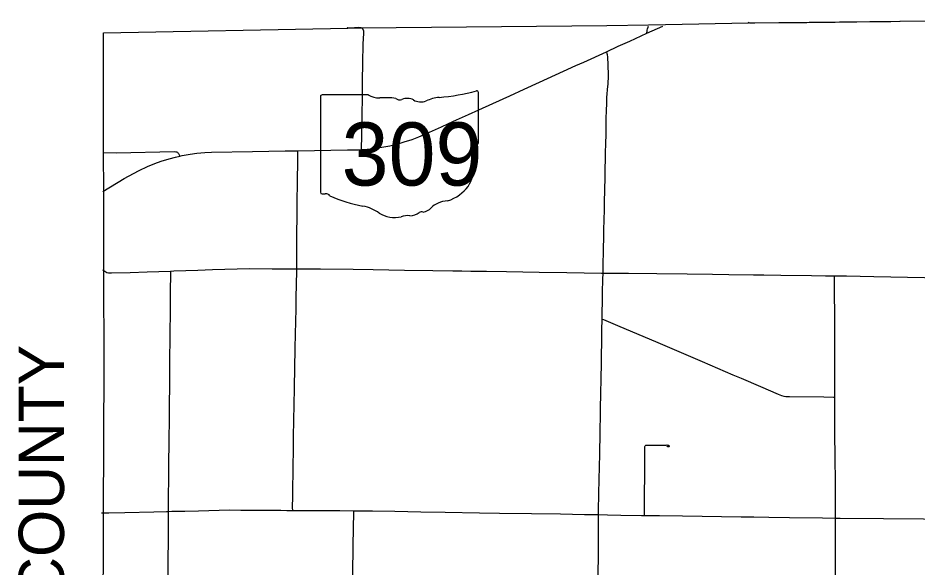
# Model space of a CAD drawing. Extents: x 9078 to 9739, y 4248 to 4966.
# Drawn here: x 9197.5 to 9296.8, y 4760.2 to 4820.8 of the extents above; entities that cross this region are included whole.
import ezdxf

# ---------------------------------------------------------------- set-up
doc = ezdxf.new("R2010")
doc.units = 0
for name, color, linetype in [('GM_X_Adjacent_County_Text', 7, 'Continuous'), ('GM_X_County', 7, 'Continuous'), ('GM_X_County_Road', 7, 'Continuous'), ('GM_X_State_Route', 7, 'Continuous'), ('GM_X_State_Shield', 7, 'Continuous'), ('GM_X_Township', 7, 'Continuous'), ('GM_X_Township_Road', 7, 'Continuous')]:
    doc.layers.add(name, color=color, linetype=linetype)

msp = doc.modelspace()

# ---------------------------------------------------------------- linework, layer by layer
at = {"layer": 'GM_X_County'}
msp.add_lwpolyline([(9206.245, 4660.249), (9206.809, 4712.196), (9206.887, 4739.703), (9206.961, 4766.011), (9207.008, 4782.44), (9206.987, 4792.874), (9206.968, 4801.71), (9206.96, 4805.912), (9206.933, 4819.119), (9233.899, 4819.643), (9235.353, 4819.689), (9262.437, 4819.962), (9267.039, 4820.02), (9268.93, 4820.044), (9278.09, 4820.249), (9301.491, 4820.507)], dxfattribs=at)
at = {"layer": 'GM_X_County_Road'}
for points in [[(9266.867, 4819.085), (9266.875, 4819.184), (9266.884, 4819.265), (9266.892, 4819.336), (9266.906, 4819.423), (9266.948, 4819.575), (9267.002, 4819.746), (9267.046, 4819.869)], [(9262.03, 4792.621), (9262.033, 4792.748), (9262.033, 4793.241), (9262.087, 4795.371), (9262.109, 4796.519), (9262.124, 4797.339), (9262.154, 4798.569), (9262.179, 4799.553), (9262.199, 4800.455), (9262.259, 4803.161), (9262.277, 4804.227), (9262.291, 4805.13), (9262.313, 4806.032), (9262.331, 4806.77), (9262.363, 4808.081), (9262.376, 4808.819), (9262.393, 4809.807), (9262.417, 4810.457), (9262.44, 4811.441), (9262.455, 4812.014), (9262.475, 4812.424), (9262.51, 4812.833), (9262.561, 4813.239), (9262.59, 4813.444), (9262.617, 4813.749), (9262.644, 4814.13), (9262.653, 4814.399), (9262.635, 4814.754), (9262.607, 4815.305), (9262.585, 4815.866), (9262.576, 4816.211), (9262.558, 4816.503), (9262.54, 4816.7), (9262.507, 4816.819), (9262.475, 4816.894), (9262.408, 4817.054)], [(9206.838, 4793.004), (9207.079, 4792.834), (9207.202, 4792.757), (9207.329, 4792.701), (9207.502, 4792.666), (9207.825, 4792.65), (9209.876, 4792.714), (9211.761, 4792.773), (9214.354, 4792.86)], [(9214.354, 4792.86), (9214.714, 4792.872), (9217.337, 4792.962), (9218.977, 4793.027), (9221.684, 4793.108), (9223.079, 4793.126), (9225.541, 4793.112), (9227.018, 4793.11), (9228.25, 4793.107)], [(9228.25, 4793.107), (9230.874, 4793.1), (9234.484, 4793.066), (9236.7, 4793.032), (9240.14, 4792.973), (9243.258, 4792.92), (9245.472, 4792.887), (9246.457, 4792.878), (9247.441, 4792.863), (9249.164, 4792.833), (9251.379, 4792.806), (9253.184, 4792.779), (9254.988, 4792.745), (9258.024, 4792.703), (9261.879, 4792.619), (9262.03, 4792.621)], [(9261.94, 4787.57), (9261.952, 4788.236), (9261.982, 4789.548), (9261.988, 4790.537), (9262.019, 4791.94), (9262.03, 4792.621)], [(9262.03, 4792.621), (9263.028, 4792.633), (9264.833, 4792.609), (9267.951, 4792.582), (9271.314, 4792.54), (9274.104, 4792.509), (9275.909, 4792.488), (9278.616, 4792.45), (9279.764, 4792.435), (9281.652, 4792.424), (9285.016, 4792.381), (9286.574, 4792.35), (9287.552, 4792.339)], [(9287.6, 4778.956), (9287.592, 4780.367), (9287.586, 4784.141), (9287.586, 4787.26), (9287.555, 4791.199), (9287.551, 4792.182), (9287.552, 4792.339)], [(9287.552, 4792.339), (9288.871, 4792.322), (9291.906, 4792.252), (9297.485, 4792.142), (9301.094, 4792.076), (9301.315, 4792.078)], [(9261.534, 4765.997), (9261.548, 4766.423), (9261.583, 4768.309), (9261.608, 4769.868), (9261.666, 4772.656), (9261.703, 4775.035), (9261.752, 4777.167), (9261.768, 4778.233), (9261.775, 4778.807), (9261.792, 4779.708), (9261.813, 4780.61), (9261.83, 4781.348), (9261.848, 4782.331), (9261.87, 4783.561), (9261.891, 4785.038), (9261.917, 4786.35), (9261.94, 4787.57)], [(9261.94, 4787.57), (9262.083, 4787.51), (9263.903, 4786.754), (9267.832, 4785.079), (9272.963, 4782.878), (9276.361, 4781.431), (9277.267, 4781.043), (9279.381, 4780.139), (9281.338, 4779.286), (9281.722, 4779.141), (9281.96, 4779.077), (9282.203, 4779.037), (9282.613, 4779.011), (9286.391, 4778.975), (9287.458, 4778.958), (9287.6, 4778.956)], [(9287.676, 4765.616), (9287.674, 4765.813), (9287.666, 4767.372), (9287.664, 4767.864), (9287.65, 4769.176), (9287.651, 4770.161), (9287.63, 4771.706), (9287.623, 4772.607), (9287.613, 4773.104), (9287.617, 4773.151), (9287.615, 4773.31), (9287.612, 4773.963), (9287.605, 4774.706), (9287.6, 4774.87), (9287.598, 4775.362), (9287.597, 4776.182), (9287.598, 4777.413), (9287.603, 4778.561), (9287.6, 4778.956)], [(9214.117, 4766.345), (9214.473, 4766.365), (9215.934, 4766.389), (9217.41, 4766.416), (9218.558, 4766.446), (9220.854, 4766.507), (9222.084, 4766.497), (9223.642, 4766.493), (9225.282, 4766.47), (9226.513, 4766.47), (9227.168, 4766.464), (9227.814, 4766.457)], [(9227.814, 4766.457), (9228.399, 4766.451), (9229.957, 4766.451), (9231.68, 4766.445), (9232.992, 4766.444), (9234.551, 4766.426)], [(9234.551, 4766.426), (9235.206, 4766.419), (9236.601, 4766.4), (9239.061, 4766.361), (9241.932, 4766.309), (9244.639, 4766.267), (9248.411, 4766.208), (9250.626, 4766.167), (9254.153, 4766.105), (9257.352, 4766.066), (9259.976, 4766.011), (9261.534, 4765.997)], [(9261.375, 4739.312), (9261.377, 4739.518), (9261.383, 4740.831), (9261.394, 4742.225), (9261.402, 4742.963), (9261.412, 4744.194), (9261.418, 4745.588), (9261.425, 4746.819), (9261.437, 4748.213), (9261.443, 4749.28), (9261.447, 4750.592), (9261.459, 4752.396), (9261.467, 4753.053), (9261.472, 4754.939), (9261.477, 4756.498), (9261.482, 4757.318), (9261.496, 4758.384), (9261.508, 4759.779), (9261.518, 4761.173), (9261.517, 4762.568), (9261.542, 4765.275), (9261.534, 4765.997)], [(9261.534, 4765.997), (9262.518, 4765.973), (9263.994, 4765.948), (9266.291, 4765.916), (9266.607, 4765.912)], [(9266.607, 4765.912), (9268.26, 4765.889), (9270.802, 4765.853), (9277.281, 4765.754), (9278.676, 4765.742), (9280.316, 4765.716), (9282.613, 4765.682), (9286.222, 4765.632), (9287.676, 4765.616)], [(9287.625, 4738.92), (9287.624, 4739.144), (9287.623, 4739.882), (9287.641, 4744.068), (9287.647, 4746.612), (9287.653, 4750.633), (9287.653, 4752.356), (9287.649, 4753.587), (9287.646, 4754.407), (9287.665, 4756.294), (9287.676, 4758.428), (9287.668, 4759.494), (9287.676, 4760.479), (9287.676, 4763.105), (9287.684, 4764.992), (9287.676, 4765.616)], [(9287.676, 4765.616), (9288.19, 4765.61), (9292.948, 4765.561), (9297.377, 4765.528), (9300.166, 4765.491), (9301.395, 4765.471), (9303.609, 4765.433), (9305.413, 4765.391), (9307.803, 4765.355)]]:
    msp.add_lwpolyline(points, dxfattribs=at)
at = {"layer": 'GM_X_State_Route'}
for points in [[(9259.047, 4815.521), (9259.899, 4815.909), (9262.408, 4817.054), (9263.706, 4817.648), (9264.977, 4818.222), (9266.246, 4818.804), (9266.867, 4819.085), (9268.642, 4819.889)], [(9243.551, 4808.483), (9244.211, 4808.781), (9245.557, 4809.388), (9247.201, 4810.133), (9248.319, 4810.649), (9249.89, 4811.357), (9251.759, 4812.203), (9253.326, 4812.919), (9255.044, 4813.701), (9257.658, 4814.89), (9259.047, 4815.521)], [(9206.877, 4801.627), (9209.244, 4803.051), (9210.239, 4803.623), (9210.894, 4803.961), (9211.786, 4804.378), (9212.62, 4804.72), (9213.314, 4804.968), (9214.175, 4805.236), (9214.887, 4805.429), (9215.375, 4805.537), (9215.607, 4805.588), (9216.493, 4805.752), (9217.224, 4805.853), (9218.121, 4805.94), (9218.858, 4805.977), (9223.37, 4806.058), (9226.98, 4806.114), (9228.379, 4806.136), (9233.872, 4806.222), (9235.022, 4806.249), (9235.41, 4806.269), (9236.006, 4806.301), (9236.741, 4806.378), (9237.635, 4806.51), (9238.523, 4806.681), (9239.322, 4806.872), (9240.111, 4807.1), (9240.969, 4807.385), (9241.737, 4807.678), (9242.565, 4808.038), (9243.551, 4808.483)]]:
    msp.add_lwpolyline(points, dxfattribs=at)
at = {"layer": 'GM_X_State_Shield'}
for p, q in [((9248.286, 4807.03), (9248.286, 4812.557)), ((9230.884, 4812.114), (9230.884, 4801.547)), ((9236.152, 4812.295), (9231.055, 4812.295)), ((9248.284, 4807.031), (9248.286, 4807.03))]:
    msp.add_line(p, q, dxfattribs=at)
for centre, major_axis, start_param, end_param in [((9242.087, 4826.701), (18.455, 0), 4.814394, 5.042369), ((9248.093, 4812.58), (0.194, 0), 6.141152, 7.989035), ((9231.083, 4812.136), (0.202, 0), 1.712693, 3.28349), ((9237.365, 4813.522), (1.955, 0), 4.042523, 4.731795), ((9238.014, 4806.363), (7.02, 0), 1.404758, 1.657858), ((9239.607, 4812.191), (0.564, 0), 3.836095, 5.185415), ((9240.435, 4810.97), (1.173, 0), 0.950623, 2.079405), ((9241.949, 4812.645), (1.411, 0), 4.081561, 5.145723), ((9244.441, 4809.068), (3.713, 0), 1.699011, 2.107814), ((9248.241, 4806.624), (0.3, 0), 1.883978, 3.671073), ((9246.334, 4805.925), (1.8, 0), 5.934695, 6.695948), ((9248.079, 4807.008), (0.207, 0), 5.05454, 6.418171), ((9243.121, 4804.014), (4.616, 0), 5.101752, 6.440018), ((9248.98, 4804.717), (1.309, 0), 2.387724, 3.262537), ((9231.085, 4801.524), (0.203, 0), 3.00124, 4.508301), ((9231.116, 4802.605), (1.552, 0), 4.665946, 4.897461), ((9231.434, 4800.938), (0.56, 0), 0.519207, 1.627899), ((9238.5, 4810.431), (13.327, 0), 4.195997, 4.488961), ((9245.067, 4798.581), (2.528, 0), 1.647645, 2.488434), ((9234.526, 4796.8), (4.17, 0), 0.823519, 1.323587), ((9241.864, 4800.523), (1.491, 0), 4.937069, 5.64225), ((9239.036, 4800.885), (2.646, 0), 4.026481, 4.996735), ((9240.565, 4797.232), (2.174, 0), 1.495662, 1.94098), ((9240.758, 4800.094), (1.41, 0), 4.691044, 5.507374), ((9242.033, 4799.071), (0.397, 0), 1.147584, 2.315152)]:
    msp.add_ellipse(centre, major_axis=major_axis, ratio=0.8, start_param=start_param, end_param=end_param, dxfattribs=at)
at = {"layer": 'GM_X_Township'}
msp.add_lwpolyline([(9206.933, 4819.119), (9233.899, 4819.643), (9235.353, 4819.689), (9262.437, 4819.962), (9267.039, 4820.02), (9268.93, 4820.044), (9278.09, 4820.249), (9301.491, 4820.507), (9314.472, 4820.654), (9327.731, 4820.757), (9343.217, 4820.773), (9342.932, 4808.852), (9342.474, 4789.454), (9342.4, 4782.335), (9342.294, 4776.852), (9341.676, 4755.756), (9341.613, 4751.456), (9313.969, 4750.869), (9313.79, 4738.291), (9313.407, 4711.5), (9313.217, 4698.184)], dxfattribs=at)
at = {"layer": 'GM_X_Township_Road'}
for points in [[(9278.005, 4820.304), (9278.058, 4820.275), (9278.12, 4820.259), (9278.201, 4820.249), (9278.774, 4820.234), (9281.644, 4820.273), (9283.038, 4820.281), (9284.513, 4820.29), (9287.629, 4820.323), (9290.006, 4820.351), (9292.956, 4820.389), (9293.446, 4820.4), (9293.774, 4820.402), (9294.757, 4820.413), (9298.856, 4820.469), (9301.482, 4820.515)], [(9234.922, 4819.695), (9234.617, 4819.676), (9234.206, 4819.649), (9234.043, 4819.657), (9233.961, 4819.663), (9233.896, 4819.676), (9233.861, 4819.69), (9233.825, 4819.711)], [(9235.599, 4819.483), (9235.585, 4819.514), (9235.563, 4819.551), (9235.536, 4819.585), (9235.5, 4819.619), (9235.435, 4819.659), (9235.353, 4819.688), (9235.271, 4819.699), (9235.11, 4819.707), (9234.922, 4819.695)], [(9235.41, 4806.269), (9235.413, 4806.488), (9235.428, 4807.636), (9235.434, 4808.538), (9235.458, 4810.014), (9235.491, 4812.065), (9235.522, 4813.787), (9235.556, 4815.837), (9235.596, 4817.888), (9235.654, 4819.116), (9235.646, 4819.302), (9235.639, 4819.348), (9235.628, 4819.405), (9235.615, 4819.445), (9235.599, 4819.483)], [(9206.894, 4805.922), (9208.333, 4805.917), (9214.763, 4806.037), (9214.929, 4806.024), (9215.013, 4806.003), (9215.092, 4805.965), (9215.161, 4805.91), (9215.215, 4805.842), (9215.255, 4805.765), (9215.375, 4805.537)], [(9228.25, 4793.107), (9228.255, 4793.695), (9228.255, 4794.105), (9228.257, 4794.536), (9228.253, 4795.575), (9228.261, 4796.229), (9228.278, 4797.058), (9228.282, 4797.695), (9228.29, 4798.172), (9228.298, 4798.591), (9228.311, 4799.258), (9228.312, 4799.757), (9228.316, 4800.741), (9228.322, 4801.314), (9228.329, 4801.806), (9228.334, 4802.297), (9228.347, 4803.363), (9228.366, 4804.429), (9228.373, 4805.494), (9228.377, 4805.952), (9228.379, 4806.136)], [(9214.117, 4766.345), (9214.125, 4767.541), (9214.142, 4770.412), (9214.148, 4771.724), (9214.162, 4772.381), (9214.184, 4773.201), (9214.197, 4774.677), (9214.213, 4776.071), (9214.231, 4777.384), (9214.24, 4778.368), (9214.244, 4780.009), (9214.254, 4781.157), (9214.257, 4782.552), (9214.274, 4783.536), (9214.291, 4785.012), (9214.292, 4785.668), (9214.302, 4786.488), (9214.318, 4787.883), (9214.329, 4788.785), (9214.334, 4789.851), (9214.341, 4790.671), (9214.355, 4792.476), (9214.355, 4792.722), (9214.354, 4792.86)], [(9228.158, 4787.56), (9228.181, 4788.448), (9228.21, 4790.088), (9228.222, 4791.236), (9228.249, 4793.039), (9228.25, 4793.107)], [(9227.811, 4767.619), (9227.829, 4769.184), (9227.85, 4770.414), (9227.864, 4771.398), (9227.889, 4773.037), (9227.912, 4774.677), (9227.948, 4776.316), (9227.977, 4778.202), (9228.004, 4779.841), (9228.045, 4782.383), (9228.083, 4784.104), (9228.119, 4786.154), (9228.144, 4787.055), (9228.158, 4787.56)], [(9266.607, 4765.912), (9266.607, 4766.055), (9266.608, 4767.695), (9266.632, 4770.894), (9266.638, 4772.124), (9266.639, 4773.273), (9266.643, 4773.379)], [(9266.643, 4773.379), (9266.648, 4773.519), (9266.672, 4773.596), (9266.735, 4773.647), (9266.813, 4773.667), (9267.141, 4773.665), (9267.287, 4773.669), (9267.504, 4773.669), (9267.948, 4773.654), (9268.149, 4773.645), (9268.24, 4773.642), (9268.636, 4773.641), (9268.866, 4773.647), (9268.935, 4773.648), (9269.01, 4773.662), (9269.09, 4773.674), (9269.116, 4773.674), (9269.145, 4773.673), (9269.169, 4773.674), (9269.194, 4773.67), (9269.219, 4773.665), (9269.244, 4773.656), (9269.267, 4773.646), (9269.283, 4773.633), (9269.297, 4773.62), (9269.304, 4773.606), (9269.313, 4773.589), (9269.315, 4773.567), (9269.318, 4773.545), (9269.316, 4773.525), (9269.313, 4773.51), (9269.303, 4773.489), (9269.287, 4773.472), (9269.268, 4773.465), (9269.243, 4773.464), (9269.213, 4773.466), (9269.196, 4773.47), (9269.175, 4773.477), (9269.142, 4773.489), (9269.124, 4773.498), (9269.107, 4773.51), (9269.079, 4773.54), (9269.067, 4773.558)], [(9227.814, 4766.457), (9227.808, 4766.561), (9227.804, 4766.643), (9227.805, 4767.135), (9227.811, 4767.619)], [(9206.722, 4766.195), (9207.549, 4766.188), (9209.282, 4766.218), (9212.499, 4766.305), (9213.901, 4766.339), (9214.117, 4766.345)], [(9214.042, 4752.966), (9214.046, 4754.006), (9214.053, 4755.647), (9214.063, 4756.877), (9214.07, 4757.944), (9214.081, 4760.076), (9214.088, 4761.307), (9214.102, 4762.865), (9214.115, 4764.752), (9214.115, 4766.065), (9214.117, 4766.345)], [(9234.354, 4753.115), (9234.359, 4753.845), (9234.37, 4754.912), (9234.396, 4756.553), (9234.408, 4757.62), (9234.441, 4759.426), (9234.481, 4762.545), (9234.513, 4764.515), (9234.547, 4766.238), (9234.551, 4766.426)]]:
    msp.add_lwpolyline(points, dxfattribs=at)

# ---------------------------------------------------------------- texts
at = {"layer": 'GM_X_Adjacent_County_Text'}
msp.add_text('MARION COUNTY', height=5, rotation=90, dxfattribs=at).set_placement((9202.594, 4727.893))
at = {"layer": 'GM_X_State_Shield'}
msp.add_text('309', height=6.961, dxfattribs=at).set_placement((9233.204, 4802.292))

doc.saveas('drawing.dxf')
